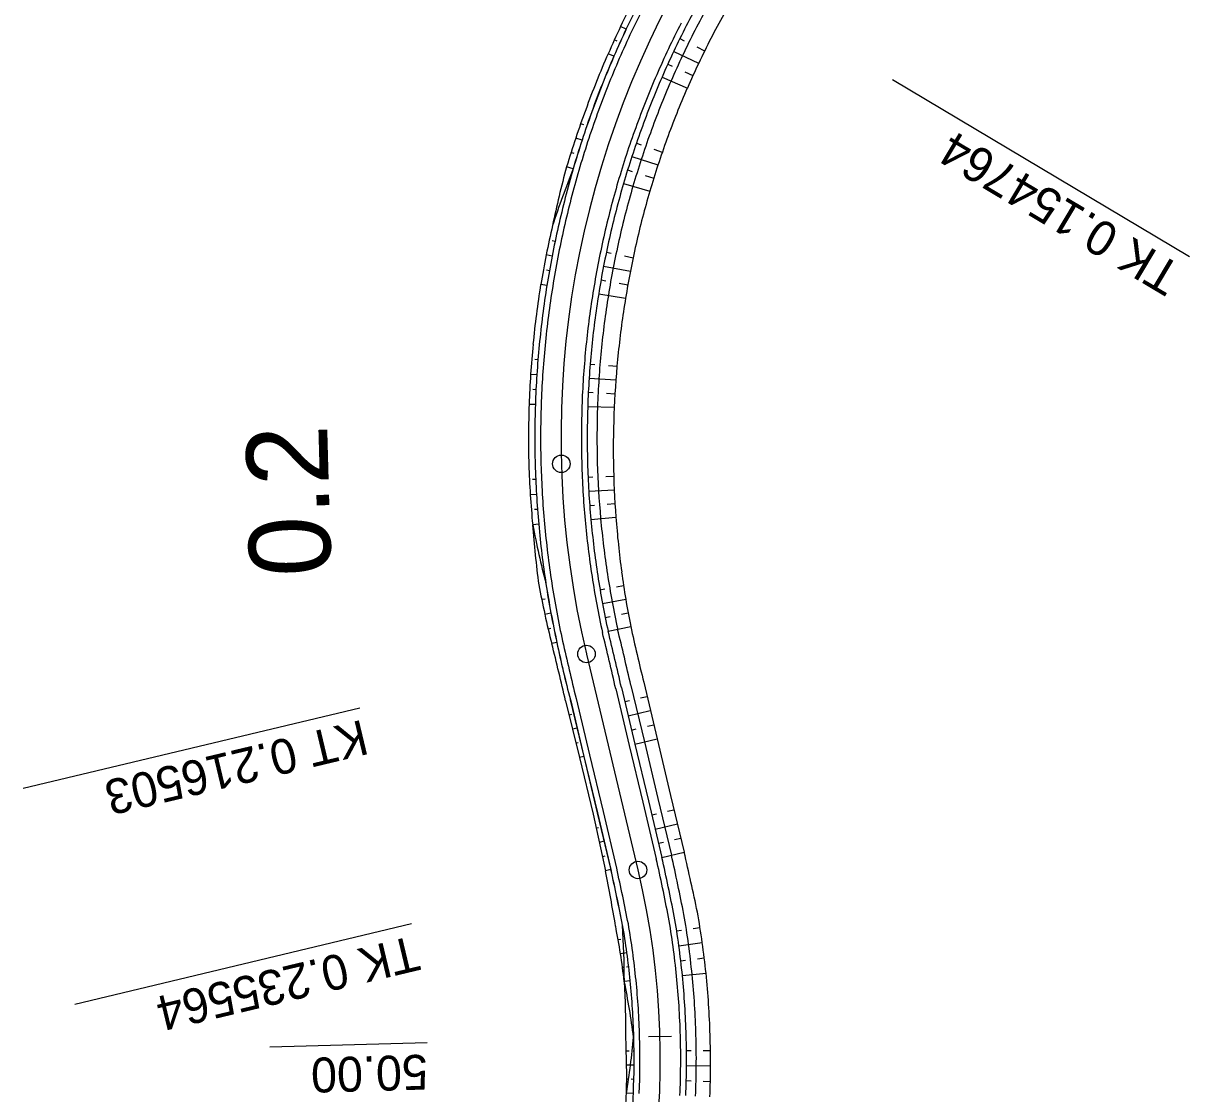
# Model space of a CAD drawing. Extents: x -481656 to -478728, y -1113199 to -1110710.
# Drawn here: x -479577.1 to -479477, y -1112599.2 to -1112507.3 of the extents above; entities that cross this region are included whole.
import ezdxf

# ---------------------------------------------------------------- set-up
doc = ezdxf.new("R2010")
doc.units = 0
for name, color, linetype in [('C1_HATCH_SLOPE_L', 7, 'Continuous'), ('C1_HATCH_SLOPE_R', 7, 'Continuous'), ('C1_HECTOMETRY', 7, 'Continuous'), ('C1_HLBODY', 7, 'Continuous'), ('C1_HRANA_TELESO', 7, 'Continuous'), ('C1_KORUNA', 7, 'Continuous'), ('C1_OSA', 7, 'Continuous'), ('C1_PRIKOP', 7, 'Continuous'), ('C1_STANICENI', 7, 'Continuous'), ('C1_VOZOVKA', 7, 'Continuous'), ('C1_ZPEVKRAJ', 7, 'Continuous')]:
    doc.layers.add(name, color=color, linetype=linetype)

msp = doc.modelspace()

# ---------------------------------------------------------------- linework, layer by layer
at = {"layer": 'C1_HATCH_SLOPE_L'}
for p, q in [((-479520.79, -1112508.65), (-479520.41, -1112508.84)), ((-479521.31, -1112509.75), (-479519.17, -1112510.76)), ((-479519.34, -1112509.36), (-479518.66, -1112509.7)), ((-479521.82, -1112510.85), (-479521.44, -1112511.02)), ((-479522.31, -1112511.96), (-479520.14, -1112512.9)), ((-479520.36, -1112511.51), (-479519.66, -1112511.83)), ((-479524.51, -1112517.62), (-479524.12, -1112517.76)), ((-479524.9, -1112518.77), (-479522.67, -1112519.5)), ((-479523.01, -1112518.14), (-479522.29, -1112518.39)), ((-479525.27, -1112519.93), (-479524.87, -1112520.06)), ((-479523.75, -1112520.4), (-479523.03, -1112520.63)), ((-479525.62, -1112521.09), (-479523.36, -1112521.75)), ((-479527.09, -1112526.99), (-479526.68, -1112527.07)), ((-479525.53, -1112527.31), (-479524.8, -1112527.47)), ((-479527.33, -1112528.18), (-479525.03, -1112528.62)), ((-479527.55, -1112529.37), (-479527.14, -1112529.45)), ((-479525.99, -1112529.65), (-479525.24, -1112529.78)), ((-479527.75, -1112530.57), (-479525.44, -1112530.94)), ((-479528.48, -1112536.6), (-479528.07, -1112536.63)), ((-479526.91, -1112536.73), (-479526.18, -1112536.79)), ((-479528.57, -1112537.81), (-479526.28, -1112537.96)), ((-479528.64, -1112539.02), (-479528.22, -1112539.04)), ((-479527.08, -1112539.1), (-479526.36, -1112539.14)), ((-479528.69, -1112540.24), (-479526.42, -1112540.31)), ((-479528.67, -1112546.31), (-479528.25, -1112546.29)), ((-479527.15, -1112546.24), (-479526.46, -1112546.21)), ((-479528.6, -1112547.52), (-479526.42, -1112547.39)), ((-479528.52, -1112548.73), (-479528.1, -1112548.7)), ((-479527.02, -1112548.62), (-479526.36, -1112548.57)), ((-479528.42, -1112549.95), (-479526.28, -1112549.75)), ((-479527.64, -1112555.97), (-479527.22, -1112555.9)), ((-479526.21, -1112555.72), (-479525.61, -1112555.62)), ((-479527.42, -1112557.16), (-479525.42, -1112556.79)), ((-479525.79, -1112558.07), (-479525.22, -1112557.96)), ((-479527.19, -1112558.35), (-479526.78, -1112558.27)), ((-479526.94, -1112559.54), (-479524.99, -1112559.12)), ((-479525.51, -1112565.58), (-479525.11, -1112565.49)), ((-479524.15, -1112565.26), (-479523.6, -1112565.13)), ((-479525.22, -1112566.8), (-479523.32, -1112566.35)), ((-479524.93, -1112568.02), (-479524.53, -1112567.92)), ((-479523.57, -1112567.69), (-479523.03, -1112567.56)), ((-479524.64, -1112569.23), (-479522.74, -1112568.78)), ((-479521.84, -1112574.99), (-479521.3, -1112574.86)), ((-479523.19, -1112575.31), (-479522.78, -1112575.21)), ((-479522.9, -1112576.53), (-479521, -1112576.07)), ((-479522.61, -1112577.74), (-479522.2, -1112577.65)), ((-479521.25, -1112577.42), (-479520.7, -1112577.29)), ((-479522.32, -1112578.96), (-479520.41, -1112578.5)), ((-479519.64, -1112585.05), (-479519.06, -1112584.96)), ((-479521.06, -1112585.27), (-479520.65, -1112585.2)), ((-479520.87, -1112586.54), (-479518.86, -1112586.27)), ((-479520.71, -1112587.82), (-479520.3, -1112587.77)), ((-479519.28, -1112587.65), (-479518.69, -1112587.58)), ((-479520.57, -1112589.1), (-479518.54, -1112588.9)), ((-479520.22, -1112595.54), (-479519.8, -1112595.54)), ((-479518.77, -1112595.53), (-479518.16, -1112595.52)), ((-479520.22, -1112596.83), (-479518.15, -1112596.85)), ((-479520.24, -1112598.12), (-479519.82, -1112598.13)), ((-479518.78, -1112598.16), (-479518.16, -1112598.18))]:
    msp.add_line(p, q, dxfattribs=at)
at = {"layer": 'C1_HATCH_SLOPE_R'}
for p, q in [((-479525.38, -1112507.83), (-479525.87, -1112507.6)), ((-479526.17, -1112508.88), (-479526.42, -1112508.77)), ((-479525.92, -1112509), (-479525.93, -1112508.99)), ((-479526.44, -1112510.17), (-479526.94, -1112509.95)), ((-479529.04, -1112516.06), (-479529.3, -1112515.98)), ((-479528.77, -1112516.16), (-479528.77, -1112516.16)), ((-479529.18, -1112517.38), (-479529.72, -1112517.2)), ((-479529.85, -1112518.51), (-479530.13, -1112518.43)), ((-479529.57, -1112518.6), (-479529.57, -1112518.6)), ((-479529.93, -1112519.83), (-479530.51, -1112519.66)), ((-479531.99, -1112525.96), (-479531.99, -1112525.96)), ((-479531.5, -1112526.06), (-479531.74, -1112526.01)), ((-479531.75, -1112527.32), (-479532.26, -1112527.23)), ((-479532.5, -1112528.5), (-479532.5, -1112528.5)), ((-479531.98, -1112528.59), (-479532.24, -1112528.54)), ((-479532.2, -1112529.85), (-479532.73, -1112529.77)), ((-479533.5, -1112536.19), (-479533.5, -1112536.19)), ((-479532.97, -1112536.23), (-479533.23, -1112536.21)), ((-479533.06, -1112537.51), (-479533.6, -1112537.48)), ((-479533.67, -1112538.77), (-479533.67, -1112538.77)), ((-479533.14, -1112538.8), (-479533.4, -1112538.78)), ((-479533.19, -1112540.08), (-479533.72, -1112540.06)), ((-479533.7, -1112546.53), (-479533.7, -1112546.53)), ((-479533.16, -1112546.51), (-479533.43, -1112546.52)), ((-479533.1, -1112547.79), (-479533.62, -1112547.82)), ((-479533.53, -1112549.11), (-479533.53, -1112549.11)), ((-479533.01, -1112549.07), (-479533.27, -1112549.09)), ((-479532.9, -1112550.35), (-479533.42, -1112550.4)), ((-479532.36, -1112556.77), (-479532.65, -1112556.82)), ((-479532.07, -1112556.72), (-479532.08, -1112556.72)), ((-479531.85, -1112557.99), (-479532.38, -1112558.09)), ((-479531.85, -1112559.3), (-479532.09, -1112559.35)), ((-479531.6, -1112559.25), (-479531.61, -1112559.25)), ((-479531.34, -1112560.51), (-479531.78, -1112560.6)), ((-479530.1, -1112566.68), (-479530.29, -1112566.73)), ((-479529.89, -1112566.63), (-479529.9, -1112566.63)), ((-479529.6, -1112567.85), (-479529.99, -1112567.94)), ((-479529.31, -1112569.06), (-479529.31, -1112569.06)), ((-479529.51, -1112569.11), (-479529.69, -1112569.15)), ((-479529.02, -1112570.28), (-479529.39, -1112570.37)), ((-479527.78, -1112576.41), (-479527.97, -1112576.45)), ((-479527.57, -1112576.36), (-479527.57, -1112576.36)), ((-479527.28, -1112577.57), (-479527.71, -1112577.67)), ((-479527.22, -1112578.84), (-479527.43, -1112578.9)), ((-479526.99, -1112578.79), (-479526.99, -1112578.79)), ((-479526.7, -1112580), (-479527.17, -1112580.12)), ((-479525.85, -1112586.01), (-479526.07, -1112586.04)), ((-479525.51, -1112585.95), (-479525.57, -1112585.96)), ((-479525.33, -1112587.15), (-479525.88, -1112587.22)), ((-479525.63, -1112588.4), (-479525.7, -1112588.41)), ((-479525.18, -1112588.35), (-479525.37, -1112588.37)), ((-479525.05, -1112589.55), (-479525.55, -1112589.6)), ((-479525.13, -1112595.59), (-479525.38, -1112595.6)), ((-479524.72, -1112595.59), (-479524.79, -1112595.59)), ((-479524.72, -1112596.8), (-479525.35, -1112596.79)), ((-479525.26, -1112598), (-479525.35, -1112597.99)), ((-479524.74, -1112598.01), (-479524.96, -1112598)), ((-479524.78, -1112599.22), (-479525.36, -1112599.19))]:
    msp.add_line(p, q, dxfattribs=at)
at = {"layer": 'C1_HECTOMETRY'}
msp.add_circle((-479530.96, -1112545.16), 0.75, dxfattribs=at)
at = {"layer": 'C1_HLBODY'}
for p, q in [((-479477.02, -1112527.4), (-479502.53, -1112512.2)), ((-479548.26, -1112566.14), (-479577.15, -1112573.03)), ((-479543.83, -1112584.67), (-479572.72, -1112591.57))]:
    msp.add_line(p, q, dxfattribs=at)
for centre in [(-479528.8, -1112561.49), (-479524.38, -1112580.03)]:
    msp.add_circle(centre, 0.75, dxfattribs=at)
at = {"layer": 'C1_HRANA_TELESO'}
for p, q in [((-479523.89, -1112563.91), (-479522.74, -1112568.78)), ((-479530.59, -1112565.51), (-479529.39, -1112570.37)), ((-479522.74, -1112568.78), (-479521.59, -1112573.65)), ((-479529.39, -1112570.37), (-479528.24, -1112575.23)), ((-479521.59, -1112573.65), (-479520.41, -1112578.5)), ((-479528.24, -1112575.23), (-479527.17, -1112580.12))]:
    msp.add_line(p, q, dxfattribs=at)
for centre, radius, start, end in [((-479451.06, -1112543.04), 75.37, 149.269, 152.85), ((-479451, -1112542.94), 82.79, 152.9406, 156.5215), ((-479451.05, -1112543.04), 75.38, 152.8503, 156.4313), ((-479451.05, -1112543.05), 82.8, 156.4382, 160.0191), ((-479451.1, -1112543.18), 75.39, 156.3246, 159.9056), ((-479451.21, -1112543.59), 82.83, 159.6276, 163.2087), ((-479451, -1112542.95), 75.4, 160.0963, 163.6772), ((-479450.6, -1112541.33), 82.8, 164.8303, 168.412), ((-479451, -1112542.93), 75.4, 163.6863, 167.2673), ((-479451.11, -1112543.53), 82.77, 166.8457, 170.4268), ((-479450.99, -1112542.93), 75.41, 167.2705, 170.8515), ((-479450.99, -1112542.88), 82.79, 170.8858, 174.4668), ((-479451.04, -1112543.28), 75.42, 170.5824, 174.1635), ((-479450.99, -1112542.88), 82.78, 174.4657, 178.0466), ((-479451.04, -1112543.58), 75.45, 173.9416, 177.5227), ((-479450.99, -1112543.05), 82.79, 177.9315, 181.5125), ((-479451, -1112543.85), 75.5, 177.318, 180.8993), ((-479450.94, -1112543.96), 75.56, 180.8167, 184.398), ((-479451.01, -1112542.57), 82.78, 181.8447, 185.4257), ((-479450.85, -1112544.18), 75.63, 184.2203, 187.8018), ((-479450.81, -1112544.56), 82.82, 184.0404, 187.6221), ((-479450.76, -1112544.23), 75.72, 187.757, 191.3386), ((-479451.54, -1112540.21), 82.79, 190.676, 194.259), ((-479340.15, -1112518.87), 189.18, 192.2848, 193.775), ((-479756.62, -1112617.43), 231.91, 12.9353, 14.1831), ((-479737.47, -1112628.79), 222.81, 11.689, 13.0438), ((-479724.82, -1112619.13), 201.46, 9.7949, 11.1667), ((-479592.42, -1112596.59), 74.28, 5.9416, 10.0341), ((-479592.28, -1112597.58), 67.2, 6.8166, 10.9099), ((-479592.45, -1112596.51), 74.3, 1.7819, 5.8745), ((-479592.58, -1112593.71), 67.16, 359.4118, 3.5074), ((-479592.46, -1112597.7), 67.11, 358.7224, 2.8158), ((-479592.47, -1112596.58), 74.32, 357.7424, 1.835), ((-479592.43, -1112595.83), 67.15, 353.0407, 357.1334)]:
    msp.add_arc(centre, radius, start, end, dxfattribs=at)
at = {"layer": 'C1_KORUNA'}
for p, q in [((-479525.8, -1112564.37), (-479524.64, -1112569.23)), ((-479530.18, -1112565.41), (-479529.02, -1112570.28)), ((-479524.64, -1112569.23), (-479523.48, -1112574.1)), ((-479529.02, -1112570.28), (-479527.86, -1112575.14)), ((-479523.48, -1112574.1), (-479522.32, -1112578.96)), ((-479527.86, -1112575.14), (-479526.7, -1112580))]:
    msp.add_line(p, q, dxfattribs=at)
for centre, radius, start, end in [((-479450.99, -1112542.91), 77.75, 149.3784, 152.9594), ((-479450.99, -1112542.91), 82.25, 152.9594, 156.5404), ((-479450.99, -1112542.91), 77.75, 152.9594, 156.5404), ((-479450.99, -1112542.91), 82.25, 156.5404, 160.1214), ((-479450.99, -1112542.91), 77.75, 156.5404, 160.1214), ((-479450.99, -1112542.91), 82.25, 160.1214, 163.7024), ((-479450.99, -1112542.91), 77.75, 160.1214, 163.7024), ((-479450.99, -1112542.91), 82.25, 163.7024, 167.2834), ((-479450.99, -1112542.91), 77.75, 163.7024, 167.2834), ((-479450.99, -1112542.91), 82.25, 167.2834, 170.8644), ((-479450.99, -1112542.91), 77.75, 167.2834, 170.8644), ((-479450.99, -1112542.91), 82.25, 170.8644, 174.4454), ((-479450.99, -1112542.91), 77.75, 170.8644, 174.4453), ((-479450.99, -1112542.91), 82.25, 174.4454, 178.0263), ((-479450.99, -1112542.91), 77.75, 174.4453, 178.0263), ((-479450.99, -1112542.91), 82.25, 178.0263, 181.6073), ((-479450.99, -1112542.91), 77.75, 178.0263, 181.6073), ((-479450.99, -1112542.91), 82.25, 181.6073, 185.1883), ((-479450.99, -1112542.91), 77.75, 181.6073, 185.1883), ((-479450.99, -1112542.91), 77.75, 185.1883, 188.7693), ((-479450.99, -1112542.91), 82.25, 185.1883, 188.7693), ((-479450.99, -1112542.91), 77.75, 188.7693, 192.3503), ((-479450.99, -1112542.91), 82.25, 188.7693, 192.3503), ((-479695.67, -1112601.88), 173.96, 12.4518, 14.0848), ((-479444.64, -1112542.66), 88.52, 191.6298, 194.894), ((-479733.94, -1112625.84), 216.75, 11.1312, 12.4903), ((-479725.12, -1112624.02), 203.25, 11.1379, 12.507), ((-479592.46, -1112596.28), 72.25, 5.7036, 9.7962), ((-479592.46, -1112596.28), 67.75, 5.7036, 9.7962), ((-479592.46, -1112596.28), 67.75, 1.6111, 5.7036), ((-479592.46, -1112596.28), 72.25, 1.6111, 5.7036), ((-479592.46, -1112596.28), 67.75, 357.5185, 1.6111), ((-479592.46, -1112596.28), 72.25, 357.5185, 1.6111), ((-479592.46, -1112596.28), 67.75, 353.426, 357.5185)]:
    msp.add_arc(centre, radius, start, end, dxfattribs=at)
at = {"layer": 'C1_OSA'}
msp.add_line((-479528.8, -1112561.49), (-479524.38, -1112580.03), dxfattribs=at)
for centre, radius, start, end in [((-479450.99, -1112542.91), 80, 149.2096, 193.4269), ((-479592.46, -1112596.28), 70, 327.8575, 13.4269)]:
    msp.add_arc(centre, radius, start, end, dxfattribs=at)
at = {"layer": 'C1_PRIKOP'}
for p, q in [((-479524.99, -1112564.18), (-479523.83, -1112569.04)), ((-479530.19, -1112565.42), (-479529.03, -1112570.28)), ((-479523.83, -1112569.04), (-479522.67, -1112573.9)), ((-479529.03, -1112570.28), (-479527.87, -1112575.14)), ((-479522.67, -1112573.9), (-479521.51, -1112578.77)), ((-479527.87, -1112575.14), (-479526.71, -1112580.01))]:
    msp.add_line(p, q, dxfattribs=at)
for centre, radius, start, end in [((-479450.99, -1112542.91), 76.91, 149.3784, 152.9594), ((-479450.99, -1112542.91), 82.26, 152.9594, 156.5404), ((-479450.99, -1112542.91), 76.91, 152.9594, 156.5404), ((-479450.99, -1112542.91), 82.26, 156.5404, 160.1214), ((-479450.99, -1112542.91), 76.91, 156.5404, 160.1214), ((-479450.99, -1112542.91), 82.26, 160.1214, 163.7024), ((-479450.99, -1112542.91), 76.91, 160.1214, 163.7024), ((-479453.29, -1112550.33), 82.5, 158.3023, 161.8992), ((-479450.99, -1112542.91), 76.91, 163.7024, 167.2834), ((-479450.99, -1112542.91), 76.91, 167.2834, 170.8644), ((-479450.99, -1112542.91), 76.91, 170.8644, 174.4453), ((-479450.99, -1112542.91), 76.91, 174.4453, 178.0263), ((-479450.99, -1112542.91), 76.91, 178.0263, 181.6073), ((-479450.99, -1112542.91), 76.91, 181.6073, 185.1883), ((-479450.99, -1112542.91), 76.91, 185.1883, 188.7693), ((-479452.37, -1112534.91), 82.51, 190.8226, 194.4211), ((-479450.99, -1112542.91), 76.91, 188.7693, 192.3503), ((-479450.99, -1112542.91), 82.26, 188.7693, 192.3503), ((-479887.22, -1112647.06), 371.59, 12.8885, 13.6505), ((-479411.39, -1112534.83), 122.67, 192.0843, 194.4395), ((-479735.58, -1112626.17), 219.26, 11.13, 12.4874), ((-479725.1, -1112624.02), 203.22, 11.1379, 12.507), ((-479592.46, -1112596.28), 73.09, 5.7036, 9.7962), ((-479593.04, -1112589.45), 67.49, 359.871, 3.9848), ((-479592.46, -1112596.28), 73.09, 1.6111, 5.7036), ((-479591.68, -1112603.1), 67.49, 7.4225, 11.5363), ((-479591.93, -1112588.29), 67.45, 350.6997, 354.8213), ((-479592.46, -1112596.28), 73.09, 357.5185, 1.6111)]:
    msp.add_arc(centre, radius, start, end, dxfattribs=at)
at = {"layer": 'C1_STANICENI'}
for p, q in [((-479542.48, -1112594.88), (-479555.98, -1112595.26)), ((-479523.49, -1112594.34), (-479521.49, -1112594.29))]:
    msp.add_line(p, q, dxfattribs=at)
at = {"layer": 'C1_VOZOVKA'}
for p, q in [((-479526.29, -1112564.49), (-479525.13, -1112569.35)), ((-479529.69, -1112565.3), (-479528.53, -1112570.16)), ((-479525.13, -1112569.35), (-479523.97, -1112574.21)), ((-479528.53, -1112570.16), (-479527.37, -1112575.02)), ((-479527.37, -1112575.02), (-479526.21, -1112579.89)), ((-479523.97, -1112574.21), (-479522.81, -1112579.07))]:
    msp.add_line(p, q, dxfattribs=at)
for centre, radius, start, end in [((-479450.99, -1112542.91), 81.75, 152.9594, 156.5404), ((-479450.99, -1112542.91), 78.25, 152.9594, 156.5404), ((-479450.99, -1112542.91), 81.75, 156.5404, 160.1214), ((-479450.99, -1112542.91), 78.25, 156.5404, 160.1214), ((-479450.99, -1112542.91), 81.75, 160.1214, 163.7024), ((-479450.99, -1112542.91), 78.25, 160.1214, 163.7024), ((-479450.99, -1112542.91), 81.75, 163.7024, 167.2834), ((-479450.99, -1112542.91), 78.25, 163.7024, 167.2834), ((-479450.99, -1112542.91), 81.75, 167.2834, 170.8644), ((-479450.99, -1112542.91), 78.25, 167.2834, 170.8644), ((-479450.99, -1112542.91), 81.75, 170.8644, 174.4454), ((-479450.99, -1112542.91), 78.25, 170.8644, 174.4453), ((-479450.99, -1112542.91), 81.75, 174.4454, 178.0263), ((-479450.99, -1112542.91), 78.25, 174.4453, 178.0263), ((-479450.99, -1112542.91), 81.75, 178.0263, 181.6073), ((-479450.99, -1112542.91), 78.25, 178.0263, 181.6073), ((-479450.99, -1112542.91), 81.75, 181.6073, 185.1883), ((-479450.99, -1112542.91), 78.25, 181.6073, 185.1883), ((-479450.99, -1112542.91), 78.25, 185.1883, 188.7693), ((-479450.99, -1112542.91), 81.75, 185.1883, 188.7693), ((-479450.99, -1112542.91), 78.25, 188.7693, 192.3503), ((-479450.99, -1112542.91), 81.75, 188.7693, 192.3503), ((-479646.41, -1112590.26), 122.85, 12.1092, 14.4259), ((-479055.23, -1112450.88), 488.07, 192.9672, 193.558), ((-479732.96, -1112625.63), 215.25, 11.1319, 12.4921), ((-479726.1, -1112624.22), 204.75, 11.1371, 12.505), ((-479592.46, -1112596.28), 71.75, 5.7036, 9.7962), ((-479592.46, -1112596.28), 68.25, 5.7036, 9.7962), ((-479592.46, -1112596.28), 68.25, 1.6111, 5.7036), ((-479592.46, -1112596.28), 71.75, 1.6111, 5.7036), ((-479592.46, -1112596.28), 68.25, 357.5185, 1.6111), ((-479592.46, -1112596.28), 71.75, 357.5185, 1.6111)]:
    msp.add_arc(centre, radius, start, end, dxfattribs=at)
at = {"layer": 'C1_ZPEVKRAJ'}
for p, q in [((-479526.29, -1112564.49), (-479525.13, -1112569.35)), ((-479529.69, -1112565.3), (-479528.53, -1112570.16)), ((-479525.13, -1112569.35), (-479523.97, -1112574.21)), ((-479528.53, -1112570.16), (-479527.37, -1112575.02)), ((-479527.37, -1112575.02), (-479526.21, -1112579.89)), ((-479523.97, -1112574.21), (-479522.81, -1112579.07))]:
    msp.add_line(p, q, dxfattribs=at)
for centre, radius, start, end in [((-479450.99, -1112542.91), 81.75, 152.9594, 156.5404), ((-479450.99, -1112542.91), 78.25, 152.9594, 156.5404), ((-479450.99, -1112542.91), 81.75, 156.5404, 160.1214), ((-479450.99, -1112542.91), 78.25, 156.5404, 160.1214), ((-479450.99, -1112542.91), 81.75, 160.1214, 163.7024), ((-479450.99, -1112542.91), 78.25, 160.1214, 163.7024), ((-479450.99, -1112542.91), 81.75, 163.7024, 167.2834), ((-479450.99, -1112542.91), 78.25, 163.7024, 167.2834), ((-479450.99, -1112542.91), 81.75, 167.2834, 170.8644), ((-479450.99, -1112542.91), 78.25, 167.2834, 170.8644), ((-479450.99, -1112542.91), 81.75, 170.8644, 174.4454), ((-479450.99, -1112542.91), 78.25, 170.8644, 174.4453), ((-479450.99, -1112542.91), 81.75, 174.4454, 178.0263), ((-479450.99, -1112542.91), 78.25, 174.4453, 178.0263), ((-479450.99, -1112542.91), 81.75, 178.0263, 181.6073), ((-479450.99, -1112542.91), 78.25, 178.0263, 181.6073), ((-479450.99, -1112542.91), 81.75, 181.6073, 185.1883), ((-479450.99, -1112542.91), 78.25, 181.6073, 185.1883), ((-479450.99, -1112542.91), 78.25, 185.1883, 188.7693), ((-479450.99, -1112542.91), 81.75, 185.1883, 188.7693), ((-479450.99, -1112542.91), 78.25, 188.7693, 192.3503), ((-479450.99, -1112542.91), 81.75, 188.7693, 192.3503), ((-479646.41, -1112590.26), 122.85, 12.1092, 14.4259), ((-479055.23, -1112450.88), 488.07, 192.9672, 193.558), ((-479732.96, -1112625.63), 215.25, 11.1319, 12.4921), ((-479726.1, -1112624.22), 204.75, 11.1371, 12.505), ((-479592.46, -1112596.28), 71.75, 5.7036, 9.7962), ((-479592.46, -1112596.28), 68.25, 5.7036, 9.7962), ((-479592.46, -1112596.28), 68.25, 1.6111, 5.7036), ((-479592.46, -1112596.28), 71.75, 1.6111, 5.7036), ((-479592.46, -1112596.28), 68.25, 357.5185, 1.6111), ((-479592.46, -1112596.28), 71.75, 357.5185, 1.6111)]:
    msp.add_arc(centre, radius, start, end, dxfattribs=at)

# ---------------------------------------------------------------- texts
at = {"layer": 'C1_HECTOMETRY'}
msp.add_text('0.2', height=7, rotation=91.5617, dxfattribs=at).set_placement((-479550.71, -1112554.76))
at = {"layer": 'C1_HLBODY'}
for s, height, rotation, p in [('TK 0.154764', 3, 149.2096, (-479477.53, -1112528.26)), ('KT 0.216503', 2.999, 193.4269, (-479548.02, -1112567.11)), ('TK 0.235564', 2.999, 193.4269, (-479543.6, -1112585.65))]:
    msp.add_text(s, height=height, rotation=rotation, dxfattribs=at).set_placement(p)
at = {"layer": 'C1_STANICENI'}
msp.add_text('50.00', height=2.999, rotation=181.6111, dxfattribs=at).set_placement((-479542.46, -1112595.88))

doc.saveas('drawing.dxf')
